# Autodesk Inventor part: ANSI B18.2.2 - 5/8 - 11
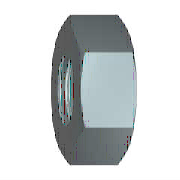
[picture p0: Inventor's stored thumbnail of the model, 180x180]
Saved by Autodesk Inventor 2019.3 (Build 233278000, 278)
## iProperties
Created: 2018-01
Part Number: ANSI B18.2.2 - 5/8 - 11
Material: Steel, Mild
Description: Hex Nuts (Inch Series) Heavy Hex Nut
Document SubType Name: Modeling
Standard: ANSI B18.2.2
Designer: u1426
Standard Revision: 2010
Standards Organization: ANSI
Language: en-US
Size Designation: 5/8 - 11
Categories: <MemberInstance><Categories><Category DisplayName="Fasteners" InternalName="e4da775c-781d-43d5-af7c-5136215cf5a6" Mnemonic="FSTN"><Category DisplayName="Nuts" I
Density: 7.85 g/cm^3
Appearance: Semi-Polished
Author: u1426
IsCustomPart: 0
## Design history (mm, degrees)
sketch "Sketch1"
  geometry: L1 (-15.574, 0)-(-7.787, 13.487); L2 (-7.787, 13.487)-(7.787, 13.487); L3 (7.787, 13.487)-(15.574, 0); L4 (15.574, 0)-(7.787, -13.487); L5 (7.787, -13.487)-(-7.787, -13.487); L6 (-7.787, -13.487)-(-15.574, 0); 2 further points
  constraints: 12 end point, 1 coincident, 1 horizontal, 11 other
  dimensions: "d0" = 31.14782 distance of L3.end L1.start (= 1.1547 x SW)
extrude "Body" new body sketch "Sketch1" distance "d1" = 15.4686 (= KOH); taper "d2" = 0 deg
sketch "Sketch2"
  geometry: L1 (0, 7.787)-(0, 15.574) reference; L2 (0, 15.574)-(15.469, 15.574) reference; L3 (15.469, 7.787)-(15.469, 15.574) reference; L4 (-3.094, 0)-(18.562, 0) reference; L5 (0.973, 15.574)-(0, 13.487); L6 (14.496, 15.574)-(15.469, 13.487)
  constraints: 4 end point, 4 point on line
  dimensions: "d3" = 25 deg angle of L1 L5 (= ANG1); "d4" = 25 deg angle of L3 L6 (= ANG2); "d5" = 26.9748 diameter of L5.end L4 (= SW0); "d6" = 26.9748 diameter of L6.end L4 (= SW01)
revolve "Chamfer1" sketch "Sketch2" stored, may be unused: angle "d7" = 90 deg
sketch "Sketch3"
  geometry: A1 r 13.487 centre (0, 0) between (-6.744, -11.68) and (6.744, -11.68) reference; 1 further point
  constraints: 1 coincident
hole "Thread" sketch "Sketch3" at (0, 0) diameter "d25" = 13.3858; stored, may be unused: countersink angle "d29" = 82 deg, drill point angle "d31" = 118 deg; dims "d26" = 6, "d27" = 4, "d28" = 2, "d30" = 8
workaxis "Work Axis1"
workplane "Work Plane1"
body "Solid1"
chamfer "Chamfer2" distance "d8" = 1.24983 (= -0.5 x GD1 + 0.5 x NND); stored, may be unused: angle "d9" = 30 deg, second distance "d40" = 1.24983 (= -0.5 x GD1 + 0.5 x NND)
chamfer "Chamfer3" distance "d10" = 1.24983 (= -0.5 x GD1 + 0.5 x NND); stored, may be unused: angle "d11" = 30 deg, second distance "d41" = 1.24983 (= -0.5 x GD1 + 0.5 x NND)
other parameters: "ANG1" = 25 deg [user parameter; used in 1 equation term], "ANG2" = 25 deg [user parameter; used in 1 equation term], "NND" = 15.875 [user parameter; used in 4 equation terms], "KOH" = 15.4686 [user parameter; used in 1 equation term], "SW" = 26.9748 [user parameter; used in 4 equation terms], "SW0" = 26.9748 (= SW) [user parameter; used in 1 equation term], "SW01" = 26.9748 (= SW) [user parameter; used in 1 equation term], "GD1" = 13.37534 (computed from THREADDIA, PTC, TOA) [user parameter; used in 4 equation terms], "d13" = 0, "d14" = 0, "d39" = 0, "d42" = 0, "THREADDIA" = 15.875 [user parameter; used in 1 equation term], "TOA" = 30 deg [user parameter; used in 1 equation term], "PTC" = 2.30909 (computed from TPU) [user parameter; used in 1 equation term], "E0" = 31.15589 (= 1.155 x SW) [user parameter]
